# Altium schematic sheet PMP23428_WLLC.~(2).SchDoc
size 431 x 279 mm; Date: Not shown in title block; ApprovedBy: Not shown in title block; CheckedBy: Not shown in title block; Author: Not shown in title block; CompanyName: Not shown in title block; Engineer: Not shown in title block; Organization: Not shown in title block; Address1: Not shown in title block; Address2: Not shown in title block; Address3: Not shown in title block; Address4: Not shown in title block; DocumentNumber: 1; Revision: Use project parameter SCH_Rev; SheetNumber: 3; SheetTotal: 4; PageSetup: Record=PageOptions¦CenterHorizontal=True¦CenterVertical=True¦PrintScale=1.00¦XCorrection=1.00¦YCorrection=1.00¦PrintKind=0¦BorderSize=5000000¦LeftOffset=0¦BottomOffset=0¦Orientation=2¦PaperLength=1000¦PaperWidth=1000¦Scale=100¦PaperSource=15¦PrintQuality=600¦MediaType=1¦DitherType=10¦PaperKind=Letter¦PrintScaleMode=1
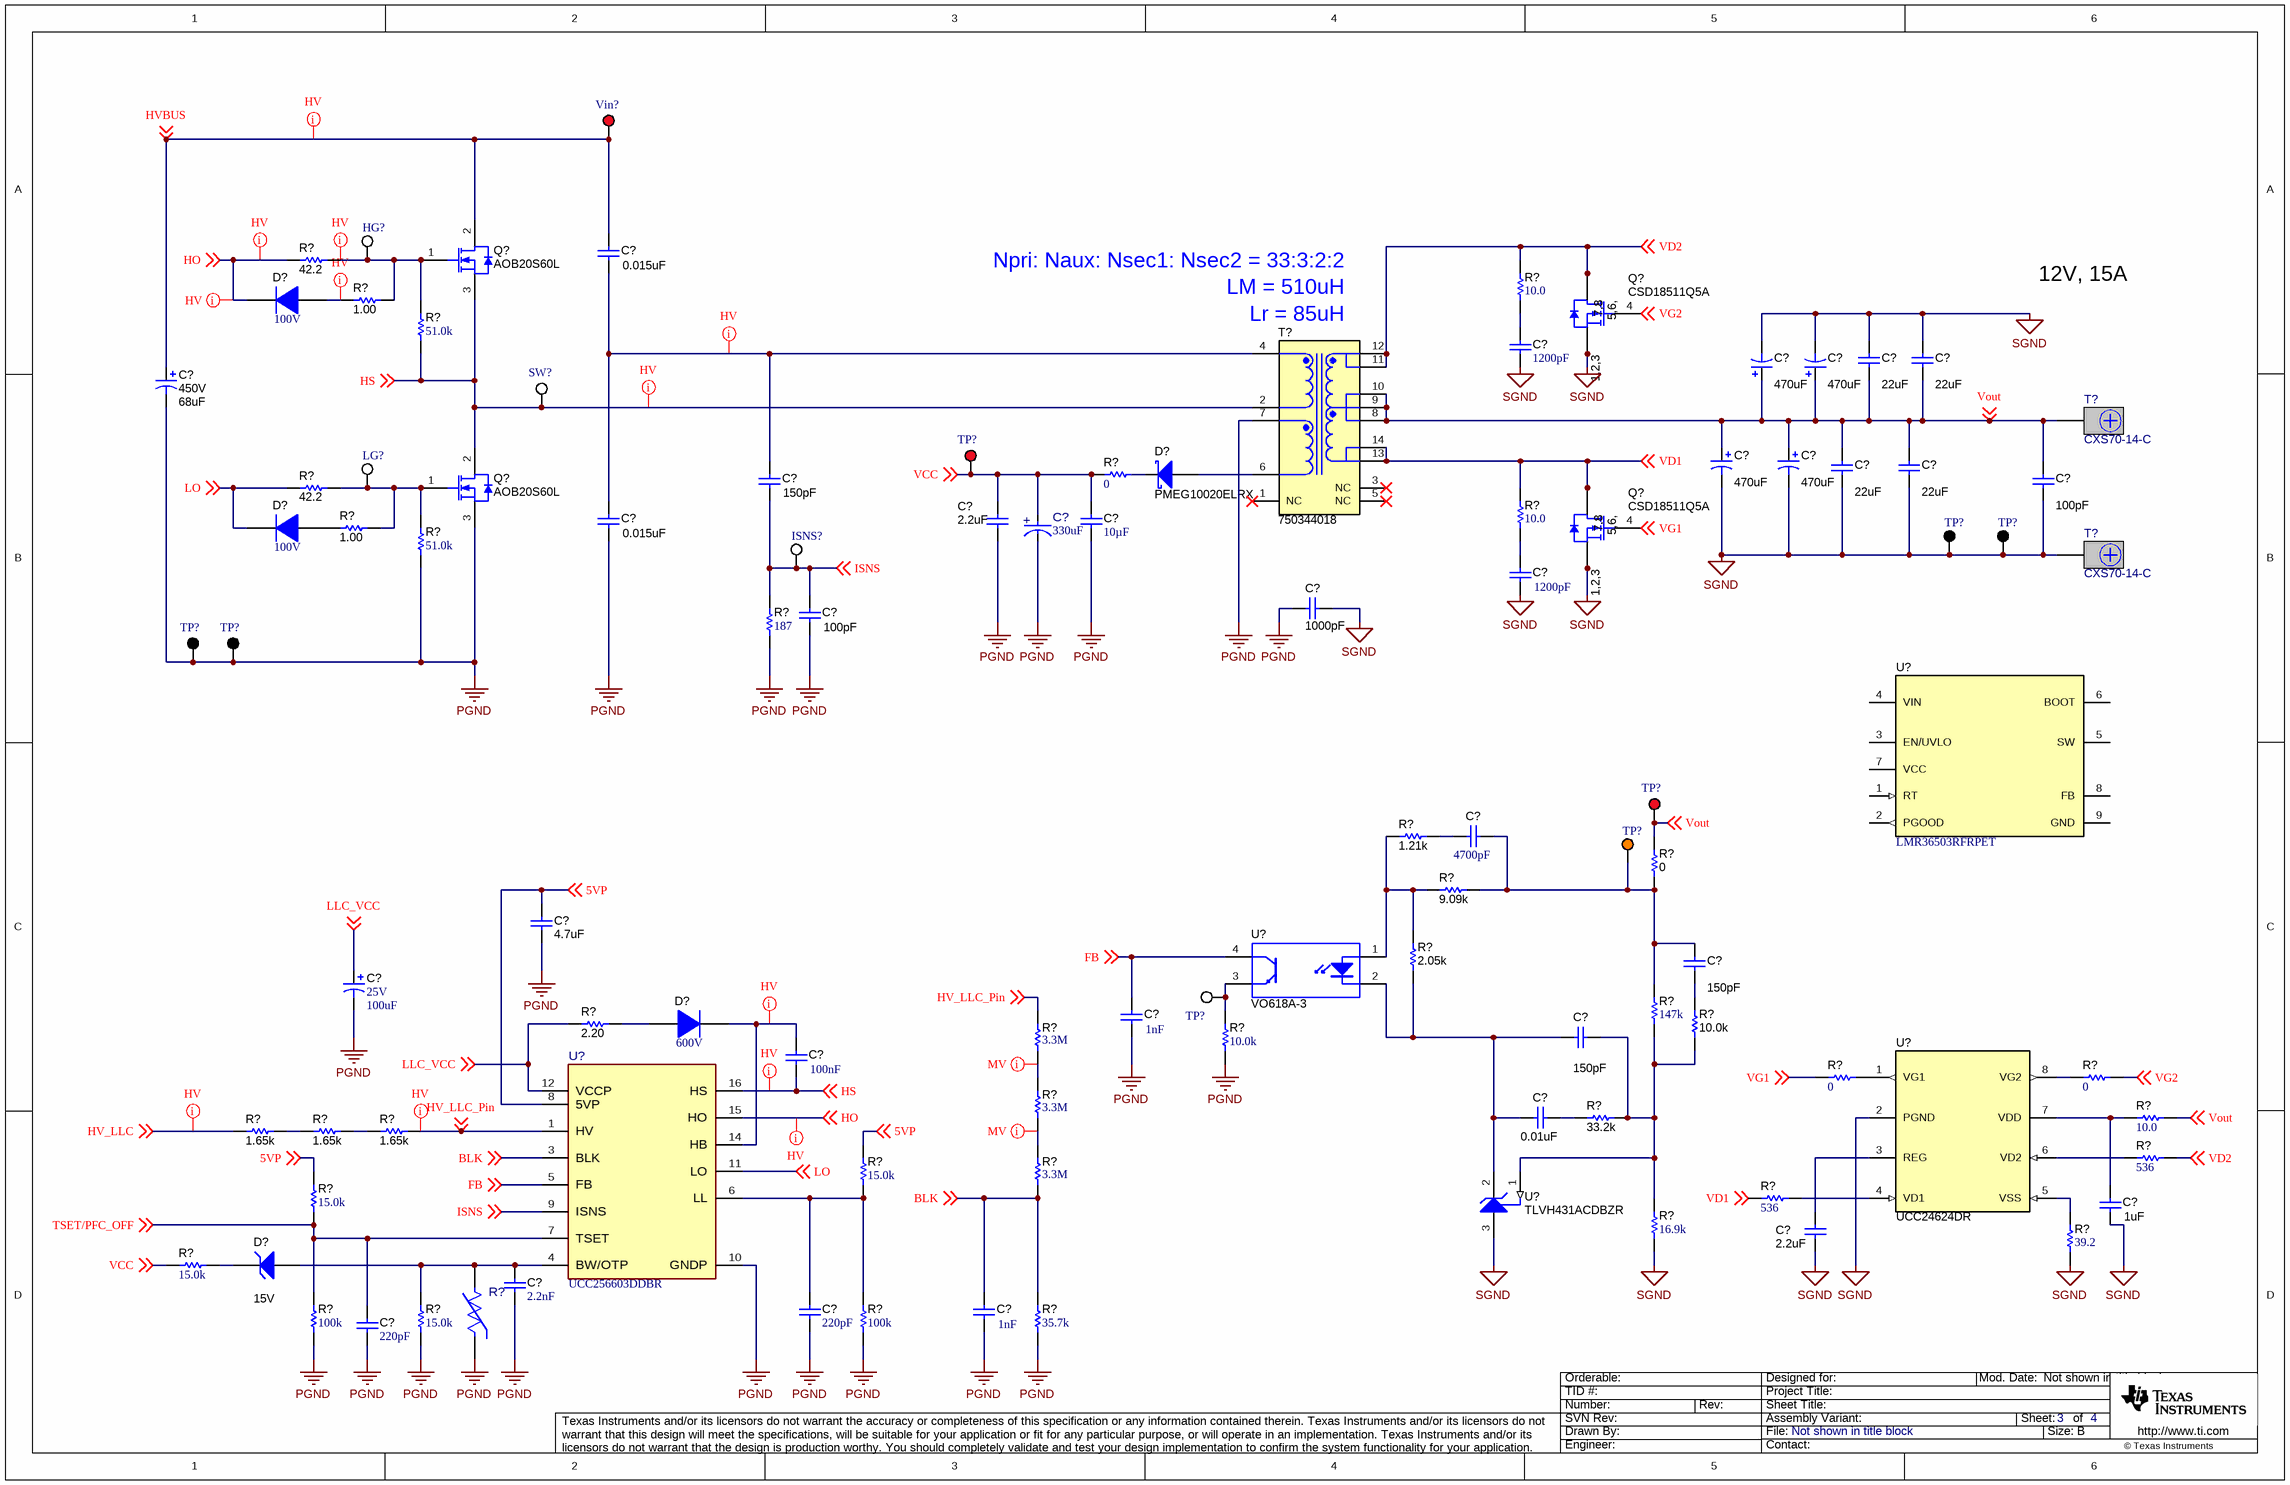
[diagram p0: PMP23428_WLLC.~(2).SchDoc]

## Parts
(Parts that share a designator on the sheet are numbered #1, #2 ... from top to bottom, then left to right.)
C?#1  ValueDisplayed: 0.015uF  [B32652_1800x700x1250]  (hidden comment: B32652A7153J000)
C?#2  ValueDisplayed: 1200pF  [0805L]  (hidden comment: GRM2165C2A122JA01D)
C?#3  ValueDisplayed: 470uF  [HW_1000x1600]  (hidden comment: UHW1V471MPD)
C?#4  ValueDisplayed: 470uF  [HW_1000x1600]  (hidden comment: UHW1V471MPD)
C?#5  ValueDisplayed: 22uF  [1206_190L]  (hidden comment: C3216X5R1E226M160AB)
C?#6  ValueDisplayed: 22uF  [1206_190L]  (hidden comment: C3216X5R1E226M160AB)
C?#7  VDC_V: 450V  ValueDisplayed: 68uF  [KXG_1800x3150]  (hidden comment: EKXG451ELL680MMN3S)
C?#8  ValueDisplayed: 470uF  [HW_1000x1600]  (hidden comment: UHW1V471MPD)
C?#9  ValueDisplayed: 470uF  [HW_1000x1600]  (hidden comment: UHW1V471MPD)
C?#10  ValueDisplayed: 22uF  [1206_190L]  (hidden comment: C3216X5R1E226M160AB)
C?#11  ValueDisplayed: 22uF  [1206_190L]  (hidden comment: C3216X5R1E226M160AB)
C?#12  ValueDisplayed: 150pF  [1206L]  (hidden comment: GRM31A5C2J151JW01D)
C?#13  ValueDisplayed: 100pF  [0603L]  (hidden comment: 06035A101FAT2A)
C?#14  ValueDisplayed: 330uF  [FP-35ZL330MEFC10X16_RADIAL-MFG]  (hidden comment: 35ZL330MEFC10X16)
C?#15  ValueDisplayed: 0.015uF  [B32652_1800x700x1250]  (hidden comment: B32652A7153J000)
C?#16  ValueDisplayed: 2.2uF  [0805L]  (hidden comment: C2012X7R1V225K085AC)
C?#17  ValueDisplayed: 10µF  [1206_180]  (hidden comment: C1206C106J3RACAUTO)
C?#18  ValueDisplayed: 1200pF  [0805L]  (hidden comment: GRM2165C2A122JA01D)
C?#19  ValueDisplayed: 1000pF  [CD45_700x600x1100]  (hidden comment: CD45-E2GA102M-NKA)
C?#20  ValueDisplayed: 100pF  [1206L]  (hidden comment: 12061A101JAT2A)
C?#21  ValueDisplayed: 4700pF  [0603L]  (hidden comment: C0603C472J1GAC7867)
C?#22  ValueDisplayed: 4.7uF  [1206L]  (hidden comment: C3216X7R1E475K085AB)
C?#23  ValueDisplayed: 150pF  [0402L]  (hidden comment: 885012005062)
C?#24  VDC_V: 25V  ValueDisplayed: 100uF  [SM_RADIAL_E]  (hidden comment: EEE-FK1E101P)
C?#25  Cap_F: 1nF  [1206L]  (hidden comment: 12061A102JAT2A)
C?#26  ValueDisplayed: 150pF  [0402L]  (hidden comment: 885012005062)
C?#27  Cap_F: 100nF  [1206_180L]  (hidden comment: GRM31C5C1E104JA01L)
C?#28  ValueDisplayed: 0.01uF  [0603L]  (hidden comment: 06031C103JAT2A)
C?#29  ValueDisplayed: 1uF  [0603L]  (hidden comment: GRM188R71C105KE15D)
C?#30  ValueDisplayed: 2.2uF  [0805L]  (hidden comment: C2012X7R1V225K085AC)
C?#31  Cap_F: 2.2nF  [0603]  (hidden comment: C0603X222K5RACTU)
C?#32  Cap_F: 220pF  [0603]  (hidden comment: C0603X221K5RACTU)
C?#33  Cap_F: 1nF  [0402L]  (hidden comment: 04025C102JAT2A)
C?#34  Cap_F: 220pF  [0603]  (hidden comment: C0603X221K5RACTU)
D?#1  Vr_V: 100V  [SOD-123]  (hidden comment: 1N4148W-7-F)
D?#2  PMEG10020ELRX  [SOD-123W]
D?#3  Vr_V: 100V  [SOD-123]  (hidden comment: 1N4148W-7-F)
D?#4  Vr_V: 600V  [SMAF]  (hidden comment: ES1JAF)
D?#5  value 15V  [SOD-123]  (hidden comment: DDZ15-7)
HG?  5012  [Keystone5012]  (value not drawn)
ISNS?  5012  [Keystone5012]  (value not drawn)
LG?  5012  [Keystone5012]  (value not drawn)
Q?#1  AOB20S60L  [DDPAK]
Q?#2  CSD18511Q5A  [DQJ0008A]
Q?#3  AOB20S60L  [DDPAK]
Q?#4  CSD18511Q5A  [DQJ0008A]
R?#1  ValueDisplayed: 42.2  [0603]  (hidden comment: RC0603FR-0742R2L)
R?#2  ValueDisplayed: 10.0  [1206L]  (hidden comment: RC1206FR-0710RL)
R?#3  ValueDisplayed: 1.00  [0603L]  (hidden comment: RC0603FR-071RL)
R?#4  ValueDisplayed: 51.0k  [0603L]  (hidden comment: RC0603FR-0751KL)
R?#5  ValueDisplayed: 0  [1206L]  (hidden comment: ERJ-8GEY0R00V)
R?#6  ValueDisplayed: 42.2  [0603L]  (hidden comment: RC0603FR-0742R2L)
R?#7  ValueDisplayed: 10.0  [1206L]  (hidden comment: RC1206FR-0710RL)
R?#8  ValueDisplayed: 1.00  [0603L]  (hidden comment: RC0603FR-071RL)
R?#9  ValueDisplayed: 51.0k  [0603L]  (hidden comment: RC0603FR-0751KL)
R?#10  ValueDisplayed: 187  [1206]  (hidden comment: RC1206FR-07187RL)
R?#11  ValueDisplayed: 1.21k  [0603L]  (hidden comment: RC0603FR-071K21L)
R?#12  ValueDisplayed: 0  [0402L]  (hidden comment: RC0402JR-070RL)
R?#13  ValueDisplayed: 9.09k  [0603L]  (hidden comment: RC0603FR-079K09L)
R?#14  ValueDisplayed: 2.05k  [0603L]  (hidden comment: RC0603FR-072K05L)
R?#15  ValueDisplayed: 147k  [0603L]  (hidden comment: RC0603FR-07147KL)
R?#16  ValueDisplayed: 2.20  [0603L]  (hidden comment: ERJ-3RQF2R2V)
R?#17  ValueDisplayed: 10.0k  [0603L]  (hidden comment: ERJ-3EKF1002V)
R?#18  Res_ohm: 3.3M  [FP-KTR18EZPF3304_1206-MFG]  (hidden comment: KTR18EZPF3304)
R?#19  ValueDisplayed: 10.0k  [0402L]  (hidden comment: ERJ-2RKF1002X)
R?#20  ValueDisplayed: 0  [0603L]  (hidden comment: RC0603JR-070RL)
R?#21  ValueDisplayed: 0  [0603L]  (hidden comment: RC0603JR-070RL)
R?#22  Res_ohm: 3.3M  [FP-KTR18EZPF3304_1206-MFG]  (hidden comment: KTR18EZPF3304)
R?#23  ValueDisplayed: 33.2k  [0603L]  (hidden comment: RC0603FR-0733K2L)
R?#24  ValueDisplayed: 10.0  [0603L]  (hidden comment: RC0603FR-0710RL)
R?#25  ValueDisplayed: 1.65k  [1206L]  (hidden comment: CRCW12061K65FKEA)
R?#26  ValueDisplayed: 1.65k  [1206L]  (hidden comment: CRCW12061K65FKEA)
R?#27  ValueDisplayed: 1.65k  [1206L]  (hidden comment: CRCW12061K65FKEA)
R?#28  ValueDisplayed: 536  [0603L]  (hidden comment: RT0603BRD07536RL)
R?#29  ValueDisplayed: 15.0k  [0603]  (hidden comment: RT0603BRD0715KL)
R?#30  Res_ohm: 3.3M  [FP-KTR18EZPF3304_1206-MFG]  (hidden comment: KTR18EZPF3304)
R?#31  ValueDisplayed: 15.0k  [0603]  (hidden comment: RT0603BRD0715KL)
R?#32  ValueDisplayed: 536  [0603L]  (hidden comment: RT0603BRD07536RL)
R?#33  ValueDisplayed: 16.9k  [0603L]  (hidden comment: RC0603FR-0716K9L)
R?#34  ValueDisplayed: 39.2  [0603L]  (hidden comment: RC0603FR-0739R2L)
R?#35  ValueDisplayed: 15.0k  [0603]  (hidden comment: RG1608P-153-B-T5)
R?#36  ValueDisplayed: 100k  [0603]  (hidden comment: RT0603BRD07100KL)
R?#37  ValueDisplayed: 15.0k  [0603]  (hidden comment: RG1608P-153-B-T5)
R?#38  ValueDisplayed: 100k  [0603]  (hidden comment: RT0603BRD07100KL)
R?#39  ValueDisplayed: 35.7k  [0603]  (hidden comment: RT0603BRD0735K7L)
R?#40  B57371V2474J060  [FP-B57371V2474J060_0603-MFG]  (value not drawn)
SW?  5012  [Keystone5012]  (value not drawn)
T?#1  750344018  [Wurth_750344018]
T?#2  CXS70-14-C  [Panduit_CXS70-14-C]
T?#3  CXS70-14-C  [Panduit_CXS70-14-C]
TP?#1  5010  [Keystone5010]  (value not drawn)
TP?#2  5011  [Keystone5011]  (value not drawn)
TP?#3  5011  [Keystone5011]  (value not drawn)
TP?#4  5011  [Keystone5011]  (value not drawn)
TP?#5  5011  [Keystone5011]  (value not drawn)
TP?#6  5010  [Keystone5010]  (value not drawn)
TP?#7  5013  [Keystone5013]  (value not drawn)
TP?#8  5012  [Keystone5012]  (value not drawn)
U?#1  LMR36503RFRPET  [RPE0009A]
U?#2  VO618A-3  [DIP-4]
U?#3  UCC256603DDBR  [DDB0014A-MFG]
U?#4  UCC24624DR  [D0008A_N]
U?#5  TLVH431ACDBZR  [DBZ0003A_N]
Vin?  5010  [Keystone5010]  (value not drawn)

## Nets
PGND: C?#7.2(-) C?#14.1(CATHODE) C?#15.2 C?#16.2 C?#17.2 C?#19.2 C?#20.2 C?#22.2 C?#24.2(-) C?#25.2 C?#31.2 C?#32.2 C?#33.2 C?#34.2 Q?#3.3(S) R?#9.1 R?#10.1 R?#19.1 R?#36.1 R?#37.1 R?#38.1 R?#39.1 R?#40.1 T?#1.7 TP?#4.1 TP?#5.1 U?#3.10(GNDP)
SGND: C?#2.2 C?#3.2(-) C?#4.2(-) C?#5.1 C?#6.1 C?#8.2(-) C?#9.2(-) C?#10.2 C?#11.2 C?#13.2 C?#18.2 C?#19.1 C?#29.2 C?#30.2 Q?#2.1(S) Q?#2.2(S) Q?#2.3(S) Q?#4.1(S) Q?#4.2(S) Q?#4.3(S) R?#33.1 R?#34.2 T?#3.1 TP?#2.1 TP?#3.1 U?#4.2(PGND) U?#5.3(ANODE)
5VP: C?#22.1 R?#29.2 R?#31.2 U?#3.8(5VP) ; off-sheet 5VP
BLK: C?#33.1 R?#30.1 R?#39.2 U?#3.3(BLK) ; off-sheet BLK
FB: C?#25.1 U?#2.4(C) U?#3.5(FB) ; off-sheet FB
HO: D?#1.1(K) R?#1.1 U?#3.15(HO) ; off-sheet HO
HS: C?#27.2 Q?#1.3(S) Q?#3.2(D) R?#4.1 SW?.1 T?#1.2 U?#3.16(HS) ; off-sheet HS
HV_LLC: R?#25.1 ; off-sheet HV_LLC
HV_LLC_Pin: R?#18.2 R?#27.2 U?#3.1(HV) ; off-sheet HV_LLC_Pin
HVBUS: C?#1.1 C?#7.1(+) Q?#1.2(D) Vin?.1 ; off-sheet HVBUS
ISNS: C?#12.2 C?#20.1 ISNS?.1 R?#10.2 U?#3.9(ISNS) ; off-sheet ISNS
LLC_VCC: C?#24.1(+) R?#16.1 U?#3.12(VCCP) ; off-sheet LLC_VCC
LO: D?#3.1(K) R?#6.1 U?#3.11(LO) ; off-sheet LO
TSET/PFC_OFF: C?#34.1 R?#31.1 R?#36.2 U?#3.7(TSET) ; off-sheet TSET/PFC_OFF
VCC: C?#14.2(ANODE) C?#16.1 C?#17.1 R?#5.1 R?#35.2 TP?#1.1 ; off-sheet VCC
VD1: Q?#4.5(D) Q?#4.6(D) Q?#4.7(D) Q?#4.8(D) Q?#4.9(D) R?#7.2 R?#32.2 T?#1.13 T?#1.14 ; off-sheet VD1
VD2: Q?#2.5(D) Q?#2.6(D) Q?#2.7(D) Q?#2.8(D) Q?#2.9(D) R?#2.2 R?#28.1 T?#1.11 T?#1.12 ; off-sheet VD2
VG1: Q?#4.4(G) R?#20.1 ; off-sheet VG1
VG2: Q?#2.4(G) R?#21.2 ; off-sheet VG2
Vout: C?#3.1(+) C?#4.1(+) C?#5.2 C?#6.2 C?#8.1(+) C?#9.1(+) C?#10.1 C?#11.1 C?#13.1 R?#12.2 R?#24.2 T?#1.8 T?#1.9 T?#1.10 T?#2.1 TP?#6.1 ; off-sheet Vout
NetC?#1_2: C?#1.2 C?#12.1 C?#15.1 T?#1.4
NetC?#2_1: C?#2.1 R?#2.1
NetC?#18_1: C?#18.1 R?#7.1
NetC?#21_1: C?#21.1 C?#23.1 R?#12.1 R?#13.2 R?#15.2 TP?#7.1
NetC?#21_2: C?#21.2 R?#11.2
NetC?#23_2: C?#23.2 R?#17.2
NetC?#26_1: C?#26.1 R?#15.1 R?#17.1 R?#23.1 R?#33.2 U?#5.1(REF)
NetC?#26_2: C?#26.2 C?#28.2 R?#14.1 U?#2.2(K) U?#5.2(CATHODE)
NetC?#27_1: C?#27.1 D?#4.1(K) U?#3.14(HB)
NetC?#28_1: C?#28.1 R?#23.2
NetC?#29_1: C?#29.1 R?#24.1 U?#4.7(VDD)
NetC?#30_1: C?#30.1 U?#4.3(REG)
NetC?#31_1: C?#31.1 D?#5.2(A) R?#37.2 R?#40.2 U?#3.4(BW/OTP)
NetC?#32_1: C?#32.1 R?#29.1 R?#38.2 U?#3.6(LL)
NetD?#1_2: D?#1.2(A) R?#3.1
NetD?#2_1: D?#2.1(K) R?#5.2
NetD?#2_2: D?#2.2(A) T?#1.6
NetD?#3_2: D?#3.2(A) R?#8.1
NetD?#4_2: D?#4.2(A) R?#16.2
NetD?#5_1: D?#5.1(K) R?#35.1
NetHG?_1: HG?.1 Q?#1.1(G) R?#1.2 R?#3.2 R?#4.2
NetLG?_1: LG?.1 Q?#3.1(G) R?#6.2 R?#8.2 R?#9.2
NetR?#11_1: R?#11.1 R?#13.1 R?#14.2 U?#2.1(A)
NetR?#18_1: R?#18.1 R?#22.2
NetR?#19_2: R?#19.2 TP?#8.1 U?#2.3(E)
NetR?#20_2: R?#20.2 U?#4.1(VG1)
NetR?#21_1: R?#21.1 U?#4.8(VG2)
NetR?#22_1: R?#22.1 R?#30.2
NetR?#25_2: R?#25.2 R?#26.1
NetR?#26_2: R?#26.2 R?#27.1
NetR?#28_2: R?#28.2 U?#4.6(VD2)
NetR?#32_1: R?#32.1 U?#4.4(VD1)
NetR?#34_1: R?#34.1 U?#4.5(VSS)

Not connected (* = marked no-connect by the designer): T?#1 1(NC)* 3(NC)* 5(NC)*; U?#1 1(RT) 2(PGOOD) 3(EN/UVLO) 4(VIN) 5(SW) 6(BOOT) 7(VCC) 8(FB) 9(GND)

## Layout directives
net class HV: HO, HS, HV_LLC, HV_LLC_Pin, HVBUS, NetC?#1_2, NetC?#27_1, NetD?#1_2, NetHG?_1
net class MV: NetR?#18_1, NetR?#22_1

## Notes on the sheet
- LM = 510uH
- Npri: Naux: Nsec1: Nsec2 = 33:3:2:2
- 12V, 15A
- (near T?#1) Lr = 85uH

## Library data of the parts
C?#1 C?#15 = CMP-0012346-3: CAP, Film, 0.015 uF, 1250 V, +/- 5%, AEC-Q200 Grade 3, TH; Manufacturer: TDK; TaMin_C: -55°C; Polarized: N; SizeAreaWB_mm2: 180; Value1: Unknown; TaMax_C: 100°C; SizeZ_mm: 12.5; SizeX_mm: 18; SizeY_mm: 7; Cap_Case: 18x7x12.5; Value2: 1250V; SizeArea_mm2: 126; CompType: Capacitor; AEC Qualified: Y; Cap_F: 15nF; VDC_V: 1.25kV; AEC Grade: 3; AEC Category: Q200
C?#2 C?#18 = CMP-0008098-2: CAP, CERM, 1200 pF, 100 V, +/- 5%, C0G/NP0, 0805; Manufacturer: MuRata; TaMin_C: -55°C; Polarized: N; SizeAreaWB_mm2: 6.75; Value1: Unknown; U/M: EA; Value: 1200pF; TaMax_C: 125°C; SizeZ_mm: 1.45; SizeX_mm: 2; SizeY_mm: 1.25; Cap_Case: 0805; Value2: 100V; SizeArea_mm2: 2.5; Cap_F: 1.2nF; AEC Category: Q200
C?#3 C?#4 C?#8 C?#9 = CMP-0010541-2: CAP, AL, 470 uF, 35 V, +/- 20%, 0.03 ohm, TH; Manufacturer: Nichicon; TaMin_C: -40°C; ESR_ohm: 0.03; Polarized: Y; SizeAreaWB_mm2: 144; U/M: EA; Value: 470uF; TaMax_C: 105°C; SizeZ_mm: 17.5; SizeX_mm: 10; Cap_Case: 10x16mm; Value2: 35V; SizeArea_mm2: 100; CompType: Capacitor; AEC Qualified: N; Cap_F: 470µF; IRMS_A: 2A; AEC Category: Q200
C?#5 C?#6 C?#10 C?#11 = CMP-0008654-2: CAP, CERM, 22 uF, 25 V, +/- 20%, X5R, 1206_190; Manufacturer: TDK; TaMin_C: -55°C; Polarized: N; SizeAreaWB_mm2: 10.92; Value1: Unknown; U/M: EA; Value: 22uF; TaMax_C: 85°C; SizeZ_mm: 1.9; SizeX_mm: 3.2; SizeY_mm: 1.6; Cap_Case: 1206; Value2: 25V; SizeArea_mm2: 5.12; CompType: Capacitor; Cap_F: 22µF; AEC Category: Q200
C?#7 = CMP-0010043-2: CAP, AL, 68 uF, 450 V, +/- 20%, TH; Manufacturer: Chemi-Con; TaMin_C: -25°C; Polarized: Y; SizeAreaWB_mm2: 400; Value1: Unknown; U/M: EA; Value: 68uF; TaMax_C: 105°C; SizeZ_mm: 33; SizeX_mm: 18; Cap_Case: 18x31.5mm; SizeArea_mm2: 324; CompType: Capacitor; Cap_F: 68µF; IRMS_A: 6.3dA; AEC Category: Q200
C?#12 = CMP-0008885-2: CAP, CERM, 150 pF, 630 V, +/- 5%, C0G/NP0, 1206; Manufacturer: MuRata; TaMin_C: -55°C; Polarized: N; SizeAreaWB_mm2: 10.92; Value1: Unknown; U/M: EA; Value: 150pF; TaMax_C: 125°C; SizeZ_mm: 1.35; SizeX_mm: 3.2; SizeY_mm: 1.6; Cap_Case: 1206; Value2: 630V; SizeArea_mm2: 5.12; CompType: Capacitor; AEC Category: Q200
C?#13 = CMP-0006762-4: CAP, CERM, 100 pF, 50 V, +/- 1%, C0G/NP0, 0603; Manufacturer: AVX; TaMin_C: -55°C; Polarized: N; SizeAreaWB_mm2: 4.68; Value1: Unknown; U/M: EA; TaMax_C: 125°C; SizeZ_mm: 1; SizeX_mm: 1.6; SizeY_mm: 0.8; Cap_Case: 0603; Value2: 50V; SizeArea_mm2: 1.28; CompType: Capacitor; Value: 100pF; AEC Category: Q200
C?#14 = CMP-0098283-1: Cap Aluminum Lytic 330uF 35V 20% (10 X 16mm) Radial 5mm 1430mA 4000h 105C Bulk; Manufacturer: Rubycon; AEC Qualified: No; Cap_F: 330µF; IRMS_A: 1.43A; SizeZ_mm: 17.5mm; Dissipation Factor: 12%; Leakage Current: 115.5uA; Life: 4000Hours; Value: 330µF
C?#16 C?#30 = CMP-0007883-2: CAP, CERM, 2.2 uF, 35 V, +/- 10%, X7R, 0805; Manufacturer: TDK; TaMin_C: -55°C; Polarized: N; SizeAreaWB_mm2: 6.75; Value1: Unknown; U/M: EA; Value: 2.2uF; TaMax_C: 125°C; SizeZ_mm: 1.45; SizeX_mm: 2; SizeY_mm: 1.25; Cap_Case: 0805; Value2: 35V; SizeArea_mm2: 2.5; CompType: Capacitor; Cap_F: 2.2µF; AEC Category: Q200
C?#17 = CMP-0081062-1: CAP, CERM, 10 µF, 25 V,+/- 5%, X7R, AEC-Q200 Grade 1, 1206; Manufacturer: Kemet; TaMin_C: -55°C; Polarized: N; SizeAreaWB_mm2: 10.92; U/M: EA; Value: 10uF; TaMax_C: 125°C; SizeZ_mm: 1.8; SizeX_mm: 3.2; SizeY_mm: 1.6; Value2: 25V; SizeArea_mm2: 5.12; AEC Qualified: Y; AEC Grade: 1; AEC Category: Q200
C?#19 = CMP-0009595-2: CAP, CERM, 1000 pF,  V, +/- 20%, E, D7xT6mm; Manufacturer: TDK; TaMin_C: -25°C; Polarized: N; SizeAreaWB_mm2: 101.2; Value1: Unknown; U/M: EA; Value: 1000pF; TaMax_C: 125°C; SizeZ_mm: 11; SizeX_mm: 10.65; SizeY_mm: 6; Cap_Case: 7x6x11mm; SizeArea_mm2: 63.9; Cap_F: 1nF; AEC Category: Q200
C?#20 = CMP-0008462-2: CAP, CERM, 100 pF, 100 V, +/- 5%, C0G/NP0, 1206; Manufacturer: AVX; TaMin_C: -55°C; ESR_ohm: 7.01d; Polarized: N; SizeAreaWB_mm2: 10.92; Value1: 0.701 ohm; U/M: EA; Value: 100pF; TaMax_C: 125°C; SizeZ_mm: 1.35; SizeX_mm: 3.2; SizeY_mm: 1.6; Cap_Case: 1206; Value2: 100V; SizeArea_mm2: 5.12; CompType: Capacitor; AEC Category: Q200
C?#21 = CMP-0006941-4: CAP, CERM, 4700 pF, 100 V, +/- 5%, C0G/NP0, 0603; Manufacturer: Kemet; TaMin_C: -55°C; Polarized: N; SizeAreaWB_mm2: 4.68; Value1: Unknown; U/M: EA; Value: 4700pF; TaMax_C: 125°C; SizeZ_mm: 1; SizeX_mm: 1.6; SizeY_mm: 0.8; Cap_Case: 0603; Value2: 100V; SizeArea_mm2: 1.28; Cap_F: 4.7nF; AEC Category: Q200
C?#22 = CMP-0008693-2: CAP, CERM, 4.7 uF, 25 V, +/- 10%, X7R, 1206; Manufacturer: TDK; TaMin_C: -55°C; Polarized: N; SizeAreaWB_mm2: 10.92; Value1: Unknown; U/M: EA; Value: 4.7uF; TaMax_C: 125°C; SizeZ_mm: 1.35; SizeX_mm: 3.2; SizeY_mm: 1.6; Cap_Case: 1206; Value2: 25V; SizeArea_mm2: 5.12; CompType: Capacitor; Cap_F: 4.7µF; AEC Category: Q200
C?#23 C?#26 = CMP-0064913-2: CAP, CERM, 150 pF, 50 V,+/- 5%, C0G/NP0, 0402; Manufacturer: Wurth Elektronik; TaMin_C: -55°C; Polarized: N; SizeAreaWB_mm2: 3; Value1: Unknown; U/M: EA; Value: 150pF; TaMax_C: 125°C; SizeZ_mm: 0.6; SizeX_mm: 1; SizeY_mm: 0.5; Cap_Case: 0402; Value2: 50V; CompType: Capacitor; AEC Category: Q200
C?#24 = CMP-0010710-1: CAP, AL, 100 uF, 25 V, +/- 20%, 0.26 ohm, AEC-Q200 Grade 2, SMD; Manufacturer: Panasonic; TaMin_C: -55°C; ESR_ohm: 2.6d; Polarized: Y; SizeAreaWB_mm2: 118.45; U/M: EA; Value: 100uF; TaMax_C: 105°C; SizeZ_mm: 6.2; SizeX_mm: 9.5; SizeY_mm: 8.3; Cap_Case: E; SizeArea_mm2: 78.85; CompType: Capacitor; Cap_F: 100µF; IRMS_A: 3dA; AEC Grade: 2; AEC Category: Q200
C?#25 = CMP-0008465-2: CAP, CERM, 1000 pF, 100 V, +/- 5%, C0G/NP0, 1206; Manufacturer: AVX; TaMin_C: -55°C; ESR_ohm: 2.38d; Polarized: N; SizeAreaWB_mm2: 10.92; Value1: 0.238 ohm; U/M: EA; Value: 1000pF; TaMax_C: 125°C; SizeZ_mm: 1.35; SizeX_mm: 3.2; SizeY_mm: 1.6; Cap_Case: 1206; Value2: 100V; SizeArea_mm2: 5.12; AEC Category: Q200
C?#27 = CMP-0064950-2: CAP, CERM, 0.1 uF, 25 V,+/- 5%, C0G/NP0, 1206; Manufacturer: MuRata; TaMin_C: -55°C; Polarized: N; SizeAreaWB_mm2: 10.92; Value1: Unknown; U/M: EA; Value: 0.1uF; TaMax_C: 125°C; SizeZ_mm: 1.8; SizeX_mm: 3.2; SizeY_mm: 1.6; Cap_Case: 1206; Value2: 25V; SizeArea_mm2: 5.12; AEC Category: Q200
C?#28 = CMP-0006726-4: CAP, CERM, 0.01 uF, 100 V, +/- 5%, X7R, 0603; Manufacturer: AVX; TaMin_C: -55°C; ESR_ohm: 0.098; Polarized: N; SizeAreaWB_mm2: 4.68; Value1: 0.098 ohm; U/M: EA; Value: 0.01uF; TaMax_C: 125°C; SizeZ_mm: 1; SizeX_mm: 1.6; SizeY_mm: 0.8; Cap_Case: 0603; Value2: 100V; SizeArea_mm2: 1.28; Cap_F: 10nF; AEC Category: Q200
C?#29 = CMP-0007380-4: CAP, CERM, 1 uF, 16 V, +/- 10%, X7R, 0603; Manufacturer: MuRata; TaMin_C: -55°C; Polarized: N; SizeAreaWB_mm2: 4.68; Value1: Unknown; U/M: EA; Value: 1uF; TaMax_C: 125°C; SizeZ_mm: 1; SizeX_mm: 1.6; SizeY_mm: 0.8; Cap_Case: 0603; Value2: 16V; SizeArea_mm2: 1.28; CompType: Capacitor; Cap_F: 1µF; AEC Category: Q200
C?#31 = CMP-0006983-4: CAP, CERM, 2200 pF, 50 V, +/- 10%, X7R, 0603; Manufacturer: Kemet; TaMin_C: -55°C; Polarized: N; SizeAreaWB_mm2: 4.68; Value1: Unknown; U/M: EA; Value: 2200pF; TaMax_C: 125°C; SizeZ_mm: 1; SizeX_mm: 1.6; SizeY_mm: 0.8; Value2: 50V; SizeArea_mm2: 1.28; AEC Category: Q200
C?#32 C?#34 = CMP-0006982-4: CAP, CERM, 220 pF, 50 V, +/- 10%, X7R, 0603; Manufacturer: Kemet; TaMin_C: -55°C; Polarized: N; SizeAreaWB_mm2: 4.68; Value1: Unknown; U/M: EA; Value: 220pF; TaMax_C: 125°C; SizeZ_mm: 1; SizeX_mm: 1.6; SizeY_mm: 0.8; Value2: 50V; SizeArea_mm2: 1.28; AEC Category: Q200
C?#33 = CMP-0861060-1: CAP, CERM, 1000 pF, 50 V,+/- 5%, X7R, 0402; Manufacturer: AVX; Value2: 50V; SizeY_mm: 0.5; AEC Category: Q200; Polarized: N; Green_Lifecycle: Active; SizeAreaWB_mm2: 3; ValueDisplayed: 1000pF; Cap_Case: 0402; Value: 1000pF; TaMin_C: -55°C; U/M: EA; Green_REACh: Passed; SizeZ_mm: 0.6; SizeX_mm: 1; TaMax_C: 125°C
D?#1 D?#3 = CMP-0029001-2: Diode, Ultrafast, 100 V, 0.15 A, SOD-123; Manufacturer: Diodes Inc.; Io_A: 150mA; Green_Lifecycle: Active; SizeAreaWB_mm2: 13.095; Green_REACh: Passed; Value1: 0.15A; TJmax_C: 150°C; Value: 100V; SizeZ_mm: 1.35; SizeX_mm: 3.85; SizeY_mm: 1.7; Vf_V: 1.25V; SizeArea_mm2: 6.545; AEC Category: Q101
D?#2 = CMP-0028977-2: Diode, Schottky, 100 V, 2 A, AEC-Q101, SOD-123W; Manufacturer: Nexperia; Io_A: 2A; SizeAreaWB_mm2: 12.15; Vr_V: 100V; TJmax_C: 175°C; Value: 100V; SizeZ_mm: 1; SizeX_mm: 3.5; SizeY_mm: 1.7; Vf_V: 830mV; Value2: 0.83V; SizeArea_mm2: 5.95; AEC Qualified: Y; AEC Category: Q101
D?#4 = CMP-0029162-2: Diode, Ultrafast, 600 V, 1 A, AEC-Q101, SMAF; Manufacturer: Fairchild Semiconductor; Io_A: 1A; Green_Lifecycle: Not Set; SizeAreaWB_mm2: 19.95; Green_REACh: Incomplete; TJmax_C: 150°C; Value: 600V; SizeZ_mm: 1; SizeX_mm: 4.7; SizeY_mm: 2.5; Vf_V: 1.7V; SizeArea_mm2: 11.75; AEC Qualified: Y; AEC Category: Q101
D?#5 = CMP-0085135-1: Diode, Zener, 15 V, 500 mW, SOD-123; Manufacturer: Diodes Inc.; SizeAreaWB_mm2: 13.095; SizeArea_mm2: 6.545; SizeY_mm: 1.7; AEC Qualified: N; SizeZ_mm: 1.35; Value1: 0.5W; SizeX_mm: 3.85; Power_W: 500mW; RJA_CperW: 425; AEC Category: Q101
HG? ISNS? LG? SW? TP?#8 = CMP-0055149-2: Test Point, Multipurpose, White, TH; Manufacturer: Keystone Electronics; CNHeader: FALSE; Green_Lifecycle: Active; Green_REACh: Passed; ContactFinish: Silver; CT: TRUE
Q?#1 Q?#3 = CMP-0001135-4: MOSFET, N-CH, 600 V, 20 A, DDPAK; Alternate Manufacturer: None; Manufacturer: AOS; SizeZ_mm: 4.445; ChType: N; Value2: 19.8 nC; VdsMax_V: 600V; SizeX_mm: 15.245; SizeAreaWB_mm2: 209.6992; SizeY_mm: 10.16; Vgs_V: 30V; QgTyp_nC: 19.8; Value: 600V; SizeArea_mm2: 154.8892; AEC Category: Q101; IdsMax_A: 20A; ChMode: Enhancement
Q?#2 Q?#4 = CMP-0000711-1: MOSFET, N-CH, 40 V, 100 A, DQJ0008A (VSONP-8); Alternate Manufacturer: None; Manufacturer: Texas Instruments; SizeZ_mm: 1.1; ChType: N; Value2: 63 nC; Value1: 0.003; VdsMax_V: 40V; SizeX_mm: 6; SizeY_mm: 4.9; Vgs_V: 20V; Value: 40V; Rdson45_ohm: 3.5m; SizeArea_mm2: 29.4; AEC Category: Q101; IdsMax_A: 100A; SizeAreaWB_mm2: 55.2; U/M: EA; QgTyp_nC: 63
R?#1 R?#6 = CMP-0023107-5: RES, 42.2, 1%, 0.1 W, 0603; Manufacturer: Yageo; Power_W: 100mW; TempCo: 100 ppm/C; Value_Code: 42R2; Value: 42.2; EIA_Code: E96; SizeX_mm: 1.6; SizeY_mm: 0.8; SizeZ_mm: 1; Value2: 0.1W; SizeArea_mm2: 1.28; CompType: Resistor; AEC Qualified: N; VDC_V: 75V; AEC Category: Q200; SizeAreaWB_mm2: 4.68
R?#2 R?#7 = CMP-0017851-2: RES, 10.0, 1%, 0.25 W, 1206; Manufacturer: Yageo America; Power_W: 250mW; TempCo: 200 ppm/C; Value_Code: 10R0; U/M: EA; Value: 10.0; EIA_Code: E96; Res_ohm: 10; SizeX_mm: 3.2; SizeY_mm: 1.6; SizeZ_mm: 1.35; Value2: 0.25W; SizeArea_mm2: 5.12; VDC_V: 200V; AEC Category: Q200
R?#3 R?#8 = CMP-0022900-4: RES, 1.00, 1%, 0.1 W, 0603; Manufacturer: Yageo; Power_W: 100mW; TempCo: 200 ppm/C; Value_Code: 1R00; Value: 1.00; EIA_Code: E96; Res_ohm: 1; SizeX_mm: 1.6; SizeY_mm: 0.8; Value2: 0.1W; SizeArea_mm2: 1.28; CompType: Resistor; AEC Qualified: N; VDC_V: 75V; AEC Category: Q200; SizeAreaWB_mm2: 4.68
R?#4 R?#9 = CMP-0023167-5: RES, 51.0 k, 1%, 0.1 W, 0603; Manufacturer: Yageo; Power_W: 100mW; TempCo: 100 ppm/C; Value_Code: 51k0; Value: 51.0k; Res_ohm: 51k; SizeX_mm: 1.6; SizeY_mm: 0.8; SizeZ_mm: 1; Value2: 0.1W; SizeArea_mm2: 1.28; AEC Qualified: N; VDC_V: 75V; AEC Category: Q200; SizeAreaWB_mm2: 4.68
R?#5 = CMP-0018748-3: RES, 0, 5%, 0.25 W, AEC-Q200 Grade 0, 1206; Manufacturer: Panasonic; Power_W: 250mW; TempCo: 600 ppm/C; Value_Code: 0000; Value: 0; EIA_Code: E24; SizeX_mm: 3.2; SizeY_mm: 1.6; SizeZ_mm: 1.35; Value2: 0.25W; SizeArea_mm2: 5.12; AEC Qualified: Y; VDC_V: 200V; AEC Category: Q200; SizeAreaWB_mm2: 10.92
R?#10 = CMP-0017949-2: RES, 187, 1%, 0.25 W, 1206; Manufacturer: Yageo America; Power_W: 250mW; TempCo: 100 ppm/C; Value_Code: 187R; U/M: EA; Value: 187; EIA_Code: E96; SizeX_mm: 3.2; SizeY_mm: 1.6; SizeZ_mm: 1.35; Value2: 0.25W; SizeArea_mm2: 5.12; VDC_V: 200V; AEC Category: Q200
R?#11 = CMP-0022871-5: RES, 1.21 k, 1%, 0.1 W, 0603; Manufacturer: Yageo; Power_W: 100mW; TempCo: 100 ppm/C; Value_Code: 1k21; Value: 1.21k; EIA_Code: E96; SizeX_mm: 1.6; SizeY_mm: 0.8; SizeZ_mm: 1; Value2: 0.1W; SizeArea_mm2: 1.28; AEC Qualified: N; VDC_V: 75V; AEC Category: Q200; SizeAreaWB_mm2: 4.68
R?#12 = CMP-0027004-2: RES, 0, 5%, 0.063 W, 0402; Manufacturer: Yageo America; Power_W: 63mW; TempCo: 200 ppm/C; Value_Code: 0000; U/M: EA; Value: 0; EIA_Code: E24; SizeX_mm: 1; SizeY_mm: 0.5; SizeZ_mm: 0.6; Value2: 0.063W; CompType: Resistor; VDC_V: 50V; AEC Category: Q200
R?#13 = CMP-0023332-5: RES, 9.09 k, 1%, 0.1 W, 0603; Manufacturer: Yageo; Power_W: 100mW; TempCo: 100 ppm/C; Value_Code: 9k09; Value: 9.09k; EIA_Code: E96; SizeX_mm: 1.6; SizeY_mm: 0.8; SizeZ_mm: 1; Value2: 0.1W; SizeArea_mm2: 1.28; AEC Qualified: N; VDC_V: 75V; AEC Category: Q200; SizeAreaWB_mm2: 4.68
R?#14 = CMP-0022981-5: RES, 2.05 k, 1%, 0.1 W, 0603; Manufacturer: Yageo; Power_W: 100mW; TempCo: 100 ppm/C; Value_Code: 2k05; Value: 2.05k; EIA_Code: E96; SizeX_mm: 1.6; SizeY_mm: 0.8; SizeZ_mm: 1; Value2: 0.1W; SizeArea_mm2: 1.28; AEC Qualified: N; VDC_V: 75V; AEC Category: Q200; SizeAreaWB_mm2: 4.68
R?#15 = CMP-0022800-4: RES, 147 k, 1%, 0.1 W, 0603; Manufacturer: Yageo; Power_W: 100mW; TempCo: 100 ppm/C; Value: 147k; EIA_Code: E96; SizeX_mm: 1.6; SizeY_mm: 0.8; SizeZ_mm: 1; Value2: 0.1W; SizeArea_mm2: 1.28; AEC Qualified: N; VDC_V: 75V; AEC Category: Q200; SizeAreaWB_mm2: 4.68
R?#16 = CMP-0022711-2: RES, 2.20, 1%, 0.1 W, 0603; Manufacturer: Panasonic; Power_W: 100mW; TempCo: 200 ppm/C; Value_Code: 2R20; U/M: EA; Value: 2.20; Res_ohm: 2.2; SizeX_mm: 1.6; SizeY_mm: 0.8; SizeZ_mm: 1; Value2: 0.1W; SizeArea_mm2: 1.28; CompType: Resistor; AEC Category: Q200
R?#17 = CMP-0022684-3: RES, 10.0 k, 1%, 0.1 W, 0603; Manufacturer: Panasonic; Power_W: 100mW; TempCo: 100 ppm/C; Value_Code: 10k0; U/M: EA; Value: 10.0k; EIA_Code: E96; Res_ohm: 10k; SizeX_mm: 1.6; SizeY_mm: 0.8; SizeZ_mm: 1; Value2: 0.1W; SizeArea_mm2: 1.28; CompType: Resistor; VDC_V: 75V; AEC Category: Q200
R?#18 R?#22 R?#30 = CMP-0087456-2: 3.3 MOhms ±1% 0.25W, 1/4W Chip Resistor 1206 (3216 Metric) Automotive AEC-Q200, High Voltage Thick Film; Manufacturer: Rohm Semiconductor; AEC Qualified: Yes; Power_W: 250mW; SizeZ_mm: 0.65mm; AEC Grade: Grade 0; TempCo: 100ppm/°C; VDC_V: 500V
R?#19 = CMP-0026658-1: RES, 10.0 k, 1%, 0.1 W, 0402; Manufacturer: Panasonic; Power_W: 100mW; TempCo: 100 ppm/C; Value_Code: 10k0; U/M: EA; Value: 10.0k; EIA_Code: E96; Res_ohm: 10k; SizeX_mm: 1; SizeY_mm: 0.5; SizeZ_mm: 0.6; Value2: 0.1W; VDC_V: 50V; AEC Category: Q200
R?#20 R?#21 = CMP-0025885-5: RES, 0, 5%, 0.1 W, 0603; Manufacturer: Yageo; Power_W: 100mW; TempCo: 200 ppm/C; Value_Code: 0000; Value: 0; EIA_Code: E24; SizeX_mm: 1.6; SizeZ_mm: 1; Value2: 0.1W; SizeArea_mm2: 1.28; AEC Qualified: N; VDC_V: 75V; AEC Category: Q200; SizeY_mm: 0.8; SizeAreaWB_mm2: 4.68
R?#23 = CMP-0023036-5: RES, 33.2 k, 1%, 0.1 W, 0603; Manufacturer: Yageo; Power_W: 100mW; TempCo: 100 ppm/C; Value_Code: 33k2; Value: 33.2k; EIA_Code: E96; SizeX_mm: 1.6; SizeY_mm: 0.8; SizeZ_mm: 1; Value2: 0.1W; SizeArea_mm2: 1.28; AEC Qualified: N; VDC_V: 75V; AEC Category: Q200; SizeAreaWB_mm2: 4.68
R?#24 = CMP-0022751-4: RES, 10.0, 1%, 0.1 W, 0603; Manufacturer: Yageo; Power_W: 100mW; TempCo: 100 ppm/C; Value_Code: 10R0; Value: 10.0; EIA_Code: E96; Res_ohm: 10; SizeX_mm: 1.6; SizeY_mm: 0.8; SizeZ_mm: 1; Value2: 0.1W; SizeArea_mm2: 1.28; AEC Qualified: N; VDC_V: 75V; AEC Category: Q200; SizeAreaWB_mm2: 4.68
R?#25-R?#27 = CMP-0016708-3: RES, 1.65 k, 1%, 0.25 W, AEC-Q200 Grade 0, 1206; Manufacturer: Vishay-Dale; Power_W: 250mW; TempCo: 100 ppm/C; Value_Code: 1k65; Value: 1.65k; EIA_Code: E96; SizeX_mm: 3.2; SizeY_mm: 1.6; SizeZ_mm: 1.35; Value2: 0.25W; SizeArea_mm2: 5.12; CompType: Resistor; AEC Qualified: Y; VDC_V: 200V; AEC Category: Q200; AEC Grade: 0
R?#28 R?#32 = CMP-0024324-2: RES, 536, 0.1%, 0.1 W, 0603; Manufacturer: Yageo America; Power_W: 100mW; TempCo: 25 ppm/C; Value_Code: 536R; U/M: EA; Value: 536; EIA_Code: E192; SizeX_mm: 1.6; SizeY_mm: 0.8; SizeZ_mm: 1; Value2: 0.1W; SizeArea_mm2: 1.28; VDC_V: 75V; AEC Category: Q200
R?#29 R?#31 = CMP-0023780-3: RES, 15.0 k, 0.1%, 0.1 W, 0603; Manufacturer: Yageo America; Power_W: 100mW; TempCo: 25 ppm/C; Value_Code: 15k0; U/M: EA; Value: 15.0k; EIA_Code: E192; Res_ohm: 15k; SizeX_mm: 1.6; SizeY_mm: 0.8; SizeZ_mm: 1; Value2: 0.1W; SizeArea_mm2: 1.28; VDC_V: 75V; AEC Category: Q200
R?#33 = CMP-0022830-5: RES, 16.9 k, 1%, 0.1 W, 0603; Manufacturer: Yageo; Power_W: 100mW; TempCo: 100 ppm/C; Value_Code: 16k9; Value: 16.9k; EIA_Code: E96; SizeX_mm: 1.6; SizeY_mm: 0.8; SizeZ_mm: 1; Value2: 0.1W; SizeArea_mm2: 1.28; AEC Qualified: N; VDC_V: 75V; AEC Category: Q200; SizeAreaWB_mm2: 4.68
R?#34 = CMP-0023074-4: RES, 39.2, 1%, 0.1 W, 0603; Manufacturer: Yageo; Power_W: 100mW; TempCo: 100 ppm/C; Value_Code: 39R2; Value: 39.2; EIA_Code: E96; SizeX_mm: 1.6; SizeY_mm: 0.8; SizeZ_mm: 1; Value2: 0.1W; SizeArea_mm2: 1.28; AEC Qualified: N; VDC_V: 75V; AEC Category: Q200; SizeAreaWB_mm2: 4.68
R?#35 R?#37 = CMP-0023441-3: RES, 15.0 k, 0.1%, 0.1 W, 0603; Manufacturer: Susumu Co Ltd; Power_W: 100mW; TempCo: 25 ppm/C; Value_Code: 15k0; U/M: EA; Value: 15.0k; EIA_Code: E192; Res_ohm: 15k; SizeX_mm: 1.6; SizeY_mm: 0.8; SizeZ_mm: 1; Value2: 0.1W; SizeArea_mm2: 1.28; VDC_V: 75V; AEC Category: Q200
R?#36 R?#38 = CMP-0023630-3: RES, 100 k, 0.1%, 0.1 W, 0603; Manufacturer: Yageo America; Power_W: 100mW; TempCo: 25 ppm/C; U/M: EA; Value: 100k; EIA_Code: E192; SizeX_mm: 1.6; SizeY_mm: 0.8; SizeZ_mm: 1; Value2: 0.1W; SizeArea_mm2: 1.28; VDC_V: 75V; AEC Category: Q200
R?#39 = CMP-0024147-3: RES, 35.7 k, 0.1%, 0.1 W, 0603; Manufacturer: Yageo America; Power_W: 100mW; TempCo: 25 ppm/C; Value_Code: 35k7; U/M: EA; Value: 35.7k; EIA_Code: E192; SizeX_mm: 1.6; SizeY_mm: 0.8; SizeZ_mm: 1; Value2: 0.1W; SizeArea_mm2: 1.28; VDC_V: 75V; AEC Category: Q200
R?#40 = CMP-0096703-1: NTC Thermistor 470k 0603 (1608 Metric); Manufacturer: TDK; AEC Qualified: No; Res_ohm: 470kΩ; Power_W: 180mW; B 25 50: 4386K; B 25 100: 4480K; SizeZ_mm: 0.9mm; B 25 85: 4455K; B Tolerance: 3%; Tolerance_%: 5%
T?#1 = CMP-0081993-1: Transformer, 510 uH, TH; Manufacturer: Wurth Elektronik; SizeAreaWB_mm2: 1732.5; SizeArea_mm2: 1569.5; AEC Qualified: N; Ns2toNp: 0.06; Lp: 510; AEC Category: Q200; Value: 510uH; SizeZ_mm: 26.5; Ind_H: 510µH; SizeY_mm: 43; LeakageInd_H: 85µH; SizeX_mm: 36.5
T?#2 T?#3 = CMP-0075010-2: Terminal 70A Lug; Manufacturer: Panduit; CNHeader: False; Green_Lifecycle: Not Set; Green_REACh: Incomplete; CompType: Screw Terminal
TP?#1 TP?#6 Vin? = CMP-0055147-2: Test Point, Multipurpose, Red, TH; Manufacturer: Keystone Electronics; CNHeader: FALSE; Green_Lifecycle: Active; Green_REACh: Passed; ContactFinish: Silver; CT: TRUE
TP?#2 TP?#3 = CMP-0055148-2: Test Point, Multipurpose, Black, TH; Manufacturer: Keystone Electronics; CNHeader: FALSE; ContactFinish: Silver; Green_REACh: Passed; Green_Lifecycle: Active; CT: TRUE
TP?#4 TP?#5 = CMP-0055148-2: Test Point, Multipurpose, Black, TH; Manufacturer: Keystone Electronics; CNHeader: FALSE; Green_Lifecycle: Active; Green_REACh: Passed; ContactFinish: Silver; CT: TRUE
TP?#7 = CMP-0055150-2: Test Point, Multipurpose, Orange, TH; Manufacturer: Keystone Electronics; CNHeader: FALSE; Green_Lifecycle: Active; Green_REACh: Passed; ContactFinish: Silver; CT: TRUE
U?#1 = CMP-0750087-1: LMR36503/06-Q1 Wide Input 60-V Synchronous, DC-DC Buck Converter, RPE0009A (VQFN-9); Alternate PartNumber: LMR36503RFRPER; Alternate Manufacturer: Texas Instruments; SizeAreaWB_mm2: 9; SizeY_mm: 2; SizeArea_mm2: 4; SizeZ_mm: 1; CompType: IC; AEC Qualified: N; AEC Category: Q200
U?#2 = CMP-0083653-1: Optocoupler, 5.3 kV, 100-200% CTR, SMT; Manufacturer: Vishay-Semiconductor; CTR (Max): 200%; SizeAreaWB_mm2: 71.064; CTR (Min): 100%; SizeZ_mm: 5; SizeX_mm: 8.8; SizeY_mm: 4.58; SizeArea_mm2: 40.304; Voltage_Isolation_Vrms: 5.3kV
U?#3 = CMP-0095299-1: 750kHz Wide VIN/VOUT Range LLC Controller Optimized for Light Load Efficiency; Manufacturer: Texas Instruments; Number Of Outputs: 2; TaMax_C: +125°C; Output Type: Other; TJmax_C: +150°C; AEC Qualified: No; Standoff Height: 0.1mm; TaMin_C: -40°C; SizeZ_mm: 1.75mm; Switching Frequency: 30-750kHz; Max Supply Voltage: 18.5V
U?#4 = CMP-0079610-1: High Performance Synchronous Rectifier Driver for LLC Resonant Converter, D0008A (SOIC-8); Alternate Manufacturer: Texas Instruments; SizeAreaWB_mm2: 56.58; SizeZ_mm: 1.75; SizeX_mm: 4.9; SizeY_mm: 6.2; SizeArea_mm2: 30.38; CompType: IC; AEC Qualified: N; AEC Category: Q200
U?#5 = CMP-0033066-1: Low-Voltage Adjustable Precision Shunt Regulator, 129 ppm / degC, 80 mA, 0 to 70 degC, 3-pin SOT-23 (DBZ), Green (RoHS & no Sb/Br); Manufacturer: Texas Instruments; Min Iz for Regulation(uA): 80; VO Adj(Max)(V): 18; VO Adj(Min)(V): 1.24; Rating: Catalog; SubFamily: Shunt Voltage Reference; Temp Coeff(Max)(ppm/ degree C): 129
